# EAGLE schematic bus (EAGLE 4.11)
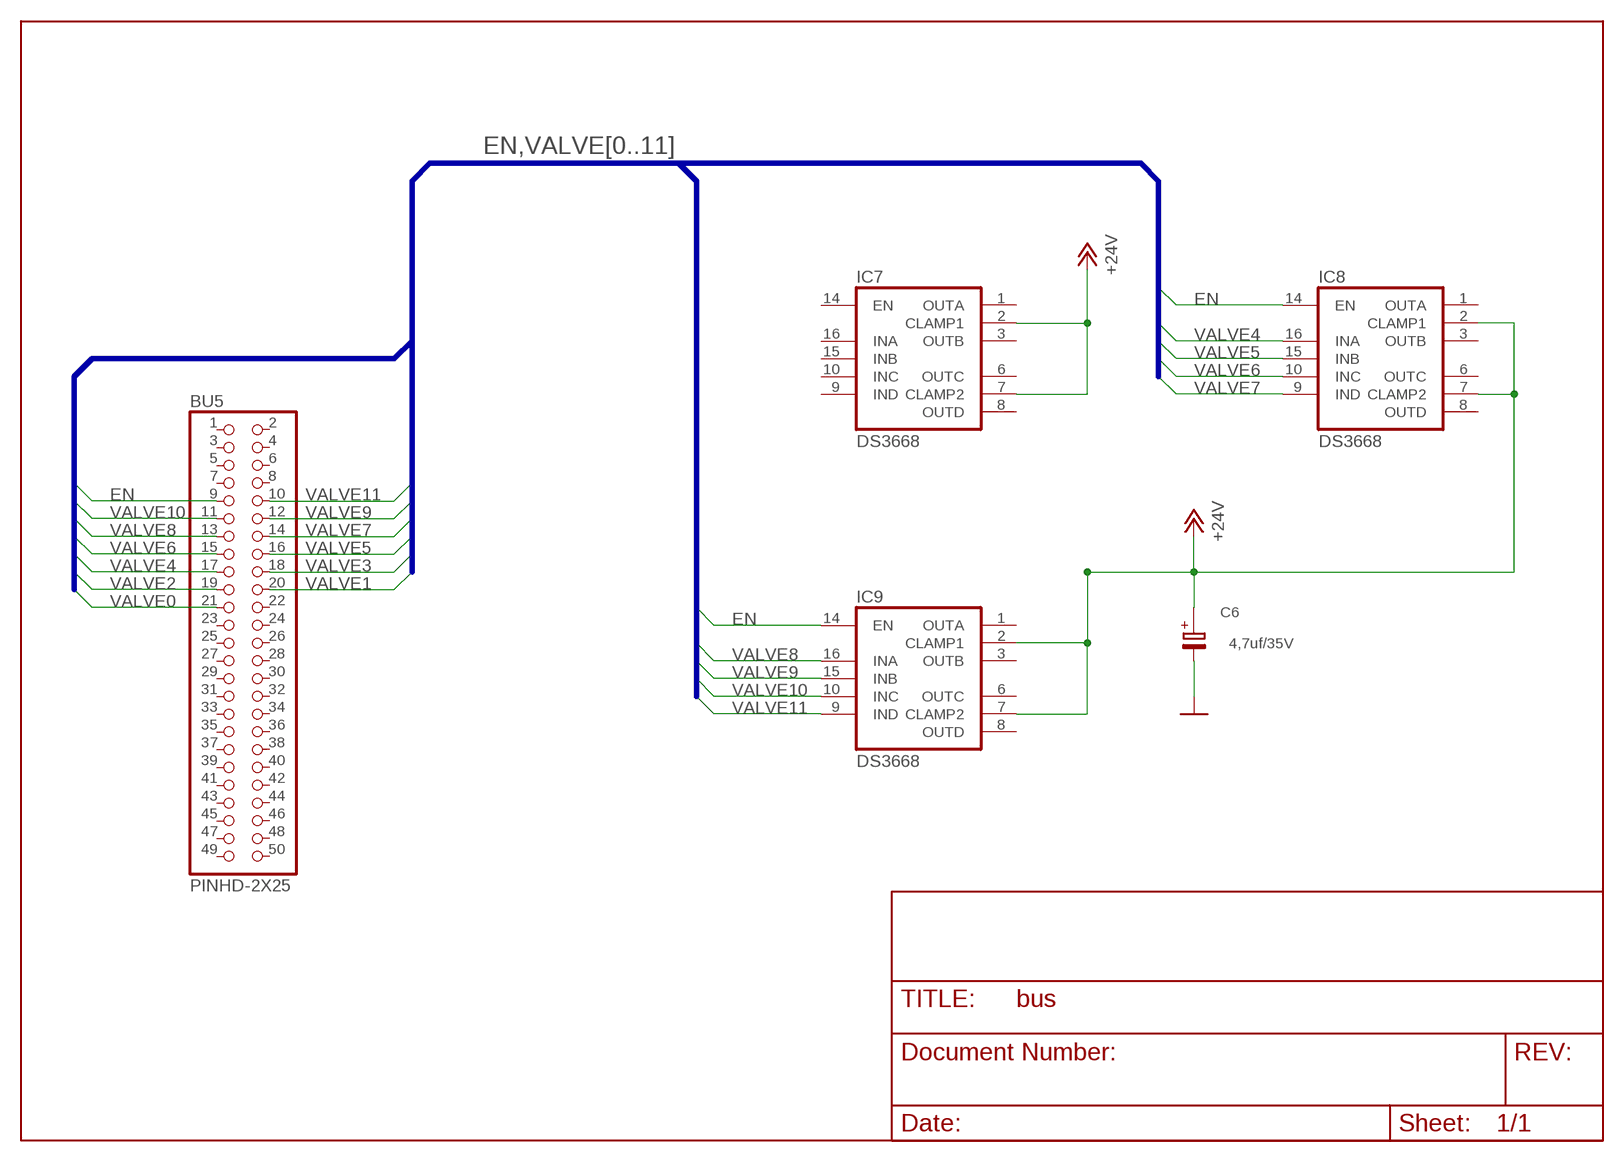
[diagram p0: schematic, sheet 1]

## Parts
BU5  PINHD-2X25  [2X25]
C6  4,7uf/35V  E2-5@1  [E2,5-5]
IC7  DS3668  [DIL-16]
IC8  DS3668  [DIL-16]
IC9  DS3668  [DIL-16]

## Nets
+24V: C6.+ IC7.2(CLAMP1) IC7.7(CLAMP2) IC8.2(CLAMP1) IC8.7(CLAMP2) IC9.2(CLAMP1) IC9.7(CLAMP2)
EN: BU5.9 IC8.14(EN) IC9.14(EN)
GND: C6.-
VALVE0: BU5.21
VALVE1: BU5.20
VALVE2: BU5.19
VALVE3: BU5.18
VALVE4: BU5.17 IC8.16(INA)
VALVE5: BU5.16 IC8.15(INB)
VALVE6: BU5.15 IC8.10(INC)
VALVE7: BU5.14 IC8.9(IND)
VALVE8: BU5.13 IC9.16(INA)
VALVE9: BU5.12 IC9.15(INB)
VALVE10: BU5.11 IC9.10(INC)
VALVE11: BU5.10 IC9.9(IND)
Unconnected: BU5.1 BU5.2 BU5.3 BU5.4 BU5.5 BU5.6 BU5.7 BU5.8 BU5.22 BU5.23 BU5.24 BU5.25 BU5.26 BU5.27 BU5.28 BU5.29 BU5.30 BU5.31 BU5.32 BU5.33 BU5.34 BU5.35 BU5.36 BU5.37 BU5.38 BU5.39 BU5.40 BU5.41 BU5.42 BU5.43 BU5.44 BU5.45 BU5.46 BU5.47 BU5.48 BU5.49 BU5.50 IC7.1(OUTA) IC7.3(OUTB) IC7.6(OUTC) IC7.8(OUTD) IC7.9(IND) IC7.10(INC) IC7.14(EN) IC7.15(INB) IC7.16(INA) IC8.1(OUTA) IC8.3(OUTB) IC8.6(OUTC) IC8.8(OUTD) IC9.1(OUTA) IC9.3(OUTB) IC9.6(OUTC) IC9.8(OUTD)

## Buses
EN,VALVE[0..11]

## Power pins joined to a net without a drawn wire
VCC: IC7.11(VCC) IC8.11(VCC) IC9.11(VCC)
VSS: IC7.4(VSS) IC7.5(VSS) IC7.12(VSS) IC7.13(VSS) IC8.4(VSS) IC8.5(VSS) IC8.12(VSS) IC8.13(VSS) IC9.4(VSS) IC9.5(VSS) IC9.12(VSS) IC9.13(VSS)

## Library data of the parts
BU5 = PINHEAD:PINHD-2X25
C6 = ELKO:E2-5@1
IC7-IC9 = klaus:DS3668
